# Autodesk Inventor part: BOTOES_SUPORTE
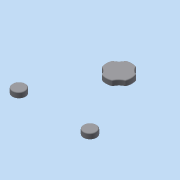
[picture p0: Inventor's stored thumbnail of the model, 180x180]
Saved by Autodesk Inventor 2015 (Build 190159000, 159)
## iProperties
Created: 2015-05
Part Number: BOTOES_SUPORTE
Material: Generic
Document SubType Name: Modeling
Designer: TREINA8
Density: 1 g/cm^3
Appearance: Default
Author: TREINA8
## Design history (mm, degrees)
sketch "Sketch1"
  geometry: C1 r 7.5 at (41, -104.5) reference; C2 r 7.5 at (-41, -104.5) reference; A1 r 15 centre (19.799, -10.201) between (6.247, -16.631) and (13.369, -23.753) reference; A2 r 15 centre (0, -30) between (13.864, -35.725) and (13.864, -24.275) reference; A3 r 1 centre (12.94, -24.656) between (13.864, -24.275) and (13.369, -23.753) reference; A4 r 1 centre (12.94, -35.344) between (13.369, -36.247) and (13.864, -35.725) reference; A5 r 15 centre (19.799, -49.799) between (13.369, -36.247) and (6.247, -43.369) reference; A6 r 1 centre (5.344, -42.94) between (5.725, -43.864) and (6.247, -43.369) reference; A7 r 15 centre (0, -30) between (-5.725, -43.864) and (5.725, -43.864) reference; A8 r 1 centre (-5.344, -42.94) between (-6.247, -43.369) and (-5.725, -43.864) reference; A9 r 15 centre (-19.799, -49.799) between (-6.247, -43.369) and (-13.369, -36.247) reference; A10 r 1 centre (-12.94, -35.344) between (-13.864, -35.725) and (-13.369, -36.247) reference; A11 r 15 centre (0, -30) between (-13.864, -24.275) and (-13.864, -35.725) reference; A12 r 1 centre (-12.94, -24.656) between (-13.369, -23.753) and (-13.864, -24.275) reference; A13 r 15 centre (-19.799, -10.201) between (-13.369, -23.753) and (-6.247, -16.631) reference; A14 r 1 centre (-5.344, -17.06) between (-5.725, -16.136) and (-6.247, -16.631) reference; A15 r 15 centre (0, -30) between (5.725, -16.136) and (-5.725, -16.136) reference; A16 r 1 centre (5.344, -17.06) between (6.247, -16.631) and (5.725, -16.136) reference; 1 further point
extrude "Extrusion1" new body sketch "Sketch1" distance "d0" = 6; taper "d1" = 0 deg
fillet "Fillet1" dims "d2" = 1
body "Solid1"
node "Reference1"
node "Reference2"
node "Reference3"
node "Reference4"
node "Reference5"
node "Reference6"
node "Reference7"
node "Reference8"
node "Reference9"
node "Reference10"
node "Reference11"
node "Reference12"
node "Reference13"
node "Reference14"
node "Reference15"
node "Reference16"
node "Reference17"
node "Reference18"
